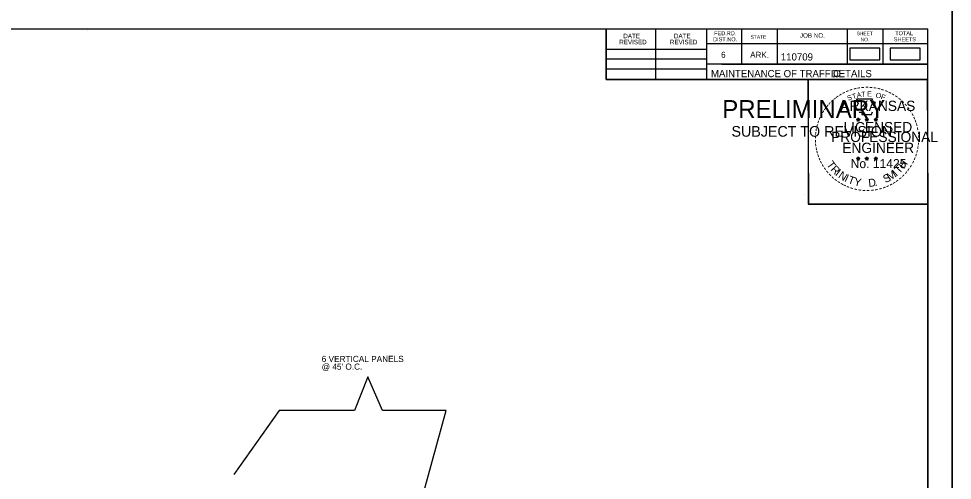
# Model space of a CAD drawing. Extents: x 2829243 to 2838161, y 467639 to 474695.
# Drawn here: x 2830244 to 2831153, y 471052 to 471502 of the extents above; entities that cross this region are included whole.
import ezdxf

# ---------------------------------------------------------------- set-up
doc = ezdxf.new("R2010")
doc.units = 0
for name, color, linetype in [('Default', 7, 'Continuous'), ('R_Border', 7, 'Continuous'), ('R_Border PE', 7, 'Continuous'), ('R_Border Prem', 7, 'Continuous'), ('R_MOT', 7, 'Continuous'), ('R_No Plot', 7, 'Continuous')]:
    doc.layers.add(name, color=color, linetype=linetype)

msp = doc.modelspace()

# ---------------------------------------------------------------- linework, layer by layer
at = {"layer": 'Default'}
for points in [[(2831053.21, 471461.81), (2831082.38, 471461.81), (2831082.38, 471473.36), (2831053.21, 471473.36)], [(2831092.56, 471461.81), (2831121.73, 471461.81), (2831121.73, 471473.36), (2831092.56, 471473.36)]]:
    msp.add_lwpolyline(points, close=True, dxfattribs=at)
at = {"layer": 'R_Border'}
for p, q in [((2829548.24, 471492.28), (2831129.14, 471492.28)), ((2830310.84, 471490.98), (2830310.84, 471490.98)), ((2830310.84, 471490.98), (2830310.84, 471490.98)), ((2830815.94, 471442.88), (2830815.94, 471492.28)), ((2830864.34, 471442.88), (2830864.34, 471492.28)), ((2830913.64, 471492.28), (2830913.64, 471442.88)), ((2830947.84, 471492.28), (2830947.84, 471457.58)), ((2830982.54, 471492.28), (2830982.54, 471457.58)), ((2831050.44, 471492.28), (2831050.44, 471457.58)), ((2831085.14, 471492.28), (2831085.14, 471457.58)), ((2831129.14, 470464.98), (2831129.14, 471492.28)), ((2831129.14, 471477.58), (2830913.64, 471477.58)), ((2831129.14, 471477.68), (2831129.14, 471477.68)), ((2830815.94, 471472.18), (2830913.64, 471472.18)), ((2830815.94, 471462.88), (2830913.64, 471462.88)), ((2831129.14, 471457.58), (2830913.64, 471457.58)), ((2830928.44, 471457.58), (2831129.14, 471457.58)), ((2830815.94, 471453.18), (2830913.64, 471453.18)), ((2831129.14, 471442.88), (2830815.94, 471442.88))]:
    msp.add_line(p, q, dxfattribs=at)
at = {"layer": 'R_Border PE'}
for p, q in [((2831059.57, 471404.16), (2831061.31, 471403.61)), ((2831059.57, 471404.16), (2831060.83, 471403.94)), ((2831059.57, 471404.16), (2831060.75, 471403.55)), ((2831060.23, 471402.12), (2831061.31, 471403.61)), ((2831060.23, 471402.12), (2831060.86, 471403.34)), ((2831060.23, 471402.12), (2831061.3, 471403.21)), ((2831061.31, 471405.43), (2831061.11, 471404.17)), ((2831062.38, 471402.12), (2831061.3, 471403.19)), ((2831061.31, 471403.61), (2831061.31, 471405.43)), ((2831061.31, 471405.43), (2831061.56, 471404.18)), ((2831063.05, 471404.16), (2831061.31, 471403.61)), ((2831062.38, 471402.12), (2831061.31, 471403.61)), ((2831063.05, 471404.16), (2831061.62, 471403.92)), ((2831062.38, 471402.12), (2831061.69, 471403.58)), ((2831063.05, 471404.16), (2831062.03, 471403.65)), ((2831067.92, 471404.16), (2831069.66, 471403.61)), ((2831067.92, 471404.16), (2831069.18, 471403.94)), ((2831067.92, 471404.16), (2831069.1, 471403.55)), ((2831068.58, 471402.12), (2831069.66, 471403.61)), ((2831068.58, 471402.12), (2831069.21, 471403.34)), ((2831068.58, 471402.12), (2831069.65, 471403.21)), ((2831069.66, 471405.43), (2831069.46, 471404.17)), ((2831070.73, 471402.12), (2831069.65, 471403.19)), ((2831069.66, 471403.61), (2831069.66, 471405.43)), ((2831069.66, 471405.43), (2831069.91, 471404.18)), ((2831071.4, 471404.16), (2831069.66, 471403.61)), ((2831070.73, 471402.12), (2831069.66, 471403.61)), ((2831071.4, 471404.16), (2831069.97, 471403.92)), ((2831070.73, 471402.12), (2831070.04, 471403.58)), ((2831071.4, 471404.16), (2831070.38, 471403.65)), ((2831076.74, 471404.1), (2831078.48, 471403.55)), ((2831076.74, 471404.1), (2831078, 471403.88)), ((2831076.74, 471404.1), (2831077.92, 471403.49)), ((2831077.4, 471402.06), (2831078.48, 471403.55)), ((2831077.4, 471402.06), (2831078.03, 471403.28)), ((2831077.4, 471402.06), (2831078.47, 471403.15)), ((2831078.48, 471405.37), (2831078.28, 471404.11)), ((2831079.55, 471402.06), (2831078.47, 471403.13)), ((2831078.48, 471403.55), (2831078.48, 471405.37)), ((2831078.48, 471405.37), (2831078.73, 471404.12)), ((2831080.22, 471404.1), (2831078.48, 471403.55)), ((2831079.55, 471402.06), (2831078.48, 471403.55)), ((2831080.22, 471404.1), (2831078.79, 471403.86)), ((2831079.55, 471402.06), (2831078.86, 471403.52)), ((2831080.22, 471404.1), (2831079.2, 471403.59)), ((2831059.55, 471366.3), (2831061.29, 471365.74)), ((2831059.55, 471366.3), (2831060.81, 471366.07)), ((2831059.55, 471366.3), (2831060.73, 471365.69)), ((2831060.21, 471364.26), (2831061.29, 471365.74)), ((2831060.21, 471364.26), (2831060.84, 471365.48)), ((2831060.21, 471364.26), (2831061.28, 471365.34)), ((2831061.29, 471367.57), (2831061.09, 471366.31)), ((2831062.36, 471364.26), (2831061.28, 471365.33)), ((2831061.29, 471365.74), (2831061.29, 471367.57)), ((2831061.29, 471367.57), (2831061.54, 471366.32)), ((2831063.03, 471366.3), (2831061.29, 471365.74)), ((2831062.36, 471364.26), (2831061.29, 471365.74)), ((2831063.03, 471366.3), (2831061.6, 471366.05)), ((2831062.36, 471364.26), (2831061.67, 471365.71)), ((2831063.03, 471366.3), (2831062.01, 471365.79)), ((2831067.89, 471366.3), (2831069.64, 471365.74)), ((2831067.89, 471366.3), (2831069.16, 471366.07)), ((2831067.89, 471366.3), (2831069.08, 471365.69)), ((2831068.56, 471364.26), (2831069.64, 471365.74)), ((2831068.56, 471364.26), (2831069.19, 471365.48)), ((2831068.56, 471364.26), (2831069.63, 471365.34)), ((2831069.64, 471367.57), (2831069.43, 471366.31)), ((2831070.7, 471364.26), (2831069.63, 471365.33)), ((2831069.64, 471365.74), (2831069.64, 471367.57)), ((2831069.64, 471367.57), (2831069.88, 471366.32)), ((2831071.37, 471366.3), (2831069.64, 471365.74)), ((2831070.7, 471364.26), (2831069.64, 471365.74)), ((2831071.37, 471366.3), (2831069.94, 471366.05)), ((2831070.7, 471364.26), (2831070.02, 471365.71)), ((2831071.37, 471366.3), (2831070.35, 471365.79)), ((2831076.73, 471366.25), (2831078.47, 471365.69)), ((2831076.73, 471366.25), (2831077.99, 471366.02)), ((2831076.73, 471366.25), (2831077.91, 471365.64)), ((2831077.39, 471364.21), (2831078.47, 471365.69)), ((2831077.39, 471364.21), (2831078.02, 471365.43)), ((2831077.39, 471364.21), (2831078.46, 471365.29)), ((2831078.47, 471367.52), (2831078.27, 471366.26)), ((2831079.54, 471364.21), (2831078.46, 471365.28)), ((2831078.47, 471365.69), (2831078.47, 471367.52)), ((2831078.47, 471367.52), (2831078.72, 471366.27)), ((2831080.21, 471366.25), (2831078.47, 471365.69)), ((2831079.54, 471364.21), (2831078.47, 471365.69)), ((2831080.21, 471366.25), (2831078.78, 471366)), ((2831079.54, 471364.21), (2831078.85, 471365.66)), ((2831080.21, 471366.25), (2831079.19, 471365.74))]:
    msp.add_line(p, q, dxfattribs=at)
for points in [[(2831059.77, 471423.55), (2831061.12, 471419.42)], [(2831077.33, 471418.94), (2831078.04, 471420.36), (2831074.61, 471420.24), (2831075.35, 471423.55), (2831059.77, 471423.55)], [(2831062.23, 471411.44), (2831062.23, 471411), (2831065.05, 471410.91), (2831064.78, 471408.54), (2831074.13, 471408.54), (2831075.13, 471411.22)], [(2831061.31, 471405.43), (2831062.38, 471402.12), (2831059.57, 471404.16), (2831063.05, 471404.16), (2831060.23, 471402.12), (2831061.31, 471405.43)], [(2831069.66, 471405.43), (2831070.73, 471402.12), (2831067.92, 471404.16), (2831071.4, 471404.16), (2831068.58, 471402.12), (2831069.66, 471405.43)], [(2831078.48, 471405.37), (2831079.55, 471402.06), (2831076.74, 471404.1), (2831080.22, 471404.1), (2831077.4, 471402.06), (2831078.48, 471405.37)], [(2831061.29, 471367.57), (2831062.36, 471364.26), (2831059.55, 471366.3), (2831063.03, 471366.3), (2831060.21, 471364.26), (2831061.29, 471367.57)], [(2831069.64, 471367.57), (2831070.7, 471364.26), (2831067.89, 471366.3), (2831071.37, 471366.3), (2831068.56, 471364.26), (2831069.64, 471367.57)], [(2831078.47, 471367.52), (2831079.54, 471364.21), (2831076.73, 471366.25), (2831080.21, 471366.25), (2831077.39, 471364.21), (2831078.47, 471367.52)]]:
    msp.add_lwpolyline(points, dxfattribs=at)
for centre, radius in [((2831061.31, 471403.6), 0.861), ((2831061.31, 471403.6), 0.723), ((2831061.31, 471403.6), 0.579), ((2831061.31, 471403.6), 0.495), ((2831061.31, 471403.6), 0.374), ((2831061.31, 471403.6), 0.248), ((2831061.31, 471403.6), 0.148), ((2831069.66, 471403.6), 0.861), ((2831069.66, 471403.6), 0.723), ((2831069.66, 471403.6), 0.579), ((2831069.66, 471403.6), 0.495), ((2831069.66, 471403.6), 0.374), ((2831069.66, 471403.6), 0.248), ((2831069.66, 471403.6), 0.148), ((2831078.48, 471403.54), 0.861), ((2831078.48, 471403.54), 0.723), ((2831078.48, 471403.54), 0.579), ((2831078.48, 471403.54), 0.495), ((2831078.48, 471403.54), 0.374), ((2831078.48, 471403.54), 0.248), ((2831078.48, 471403.54), 0.148), ((2831061.29, 471365.74), 0.861), ((2831061.29, 471365.74), 0.723), ((2831061.29, 471365.74), 0.579), ((2831061.29, 471365.74), 0.495), ((2831061.29, 471365.74), 0.374), ((2831061.29, 471365.74), 0.248), ((2831061.29, 471365.74), 0.148), ((2831069.63, 471365.74), 0.861), ((2831069.63, 471365.74), 0.723), ((2831069.63, 471365.74), 0.579), ((2831069.63, 471365.74), 0.495), ((2831069.63, 471365.74), 0.374), ((2831069.63, 471365.74), 0.248), ((2831069.63, 471365.74), 0.148), ((2831078.47, 471365.69), 0.861), ((2831078.47, 471365.69), 0.723), ((2831078.47, 471365.69), 0.579), ((2831078.47, 471365.69), 0.495), ((2831078.47, 471365.69), 0.374), ((2831078.47, 471365.69), 0.248), ((2831078.47, 471365.69), 0.148)]:
    msp.add_circle(centre, radius, dxfattribs=at)
at = {"layer": 'R_MOT'}
msp.add_lwpolyline([(2830620.35, 470975.07), (2830660.32, 471120.5), (2830598.07, 471120.5), (2830584.04, 471153.28), (2830571.05, 471120.5), (2830497.71, 471120.5), (2830453.58, 471057.96)], dxfattribs=at)
at = {"layer": 'R_No Plot'}
msp.add_line((2831009.31, 471330.61), (2831009.31, 471330.61), dxfattribs=at)
for points in [[(2829486.2, 471511.76), (2831152.9, 471511.76), (2831152.9, 470445.07), (2829486.2, 470445.07)], [(2831152.9, 471511.76), (2832819.6, 471511.76), (2832819.6, 470445.07), (2831152.9, 470445.07)], [(2830717.84, 471492.28), (2830815.94, 471492.28), (2830815.94, 471442.88), (2830896.5, 471442.88), (2831012.5, 471442.88), (2831012.5, 471321.22), (2831129.14, 471321.22), (2831129.14, 470464.98), (2829548.24, 470464.98), (2829548.24, 471492.28)], [(2831012.5, 471442.88), (2831128.54, 471442.88), (2831129.14, 471321.22), (2831013.1, 471321.22)]]:
    msp.add_lwpolyline(points, close=True, dxfattribs=at)

# ---------------------------------------------------------------- texts
at = {"layer": 'R_Border'}
for s, height, p in [('DATE', 4.396, (2830832.63, 471482.97)), ('DATE', 4.396, (2830881.93, 471482.97)), ('DIST.NO.', 3.91, (2830920.04, 471479.98)), ('FED.RD.', 3.91, (2830921.04, 471485.88)), ('STATE', 3.42, (2830956.64, 471482.48)), ('JOB NO.', 4.396, (2831004.54, 471483.48)), ('SHEET', 3.42, (2831059.74, 471485.88)), ('NO.', 3.42, (2831063.64, 471479.98)), ('SHEETS', 3.91, (2831095.94, 471479.98)), ('TOTAL', 3.91, (2831097.34, 471485.88)), ('REVISED', 4.396, (2830828.73, 471477.07)), ('REVISED', 4.396, (2830878.03, 471477.07)), ('6', 5.86, (2830927.84, 471463.88)), ('ARK.', 5.861, (2830956.14, 471463.88)), ('110709', 7, (2830986.02, 471461.28)), ('MAINTENANCE OF TRAFFIC', 7, (2830917.96, 471445.04)), (' DETAILS', 7, (2831032.95, 471445.04))]:
    msp.add_text(s, height=height, dxfattribs=at).set_placement(p)
at = {"layer": 'R_Border PE'}
for s, height, rotation, p in [('-', 8, 34.06357, (2831044.19, 471424.41)), ('-', 8, 28.79182, (2831047.18, 471426.26)), ('-', 8, 24.30721, (2831050.34, 471427.84)), ('-', 8, 19.17608, (2831053.51, 471429.19)), ('T', 5, 16.4036, (2831056.12, 471423.6)), ('-', 8, 13.63015, (2831057.26, 471430.39)), ('A', 5, 11.21318, (2831060.25, 471424.85)), ('-', 8, 10.21935, (2831060.65, 471431.2)), ('T', 5, 6.02276, (2831064.49, 471425.68)), ('-', 8, 5.89682, (2831064.3, 471431.75)), ('-', 8, 0.18623, (2831068.16, 471432.11)), ('E', 5, 0.83234, (2831070.02, 471426.23)), ('-', 8, 357.74304, (2831071.77, 471432.05)), ('-', 8, 352.16172, (2831075.49, 471431.77)), ('O', 5, 350.4515, (2831078.04, 471425.18)), ('-', 8, 347.20489, (2831079.09, 471431.2)), ('-', 8, 342.3362, (2831082.26, 471430.42)), ('-', 8, 337.85509, (2831085.94, 471429.31)), ('-', 8, 334.12109, (2831089.09, 471427.95)), ('-', 8, 329.64089, (2831091.99, 471426.54)), ('-', 8, 48.42305, (2831034.52, 471416.07)), ('-', 8, 42.96224, (2831036.76, 471418.46)), ('-', 8, 38.95066, (2831038.92, 471420.54)), ('-', 8, 36.23174, (2831041.3, 471422.43)), ('S', 5, 21.59401, (2831051.55, 471421.94)), ('F', 5, 340.07066, (2831082.81, 471424.04)), ('-', 8, 325.86266, (2831095.2, 471424.73)), ('-', 8, 320.52971, (2831098.25, 471422.6)), ('-', 8, 315.57859, (2831101.25, 471420.16)), ('-', 8, 58.07063, (2831028.81, 471408.17)), ('-', 8, 54.23247, (2831030.44, 471410.8)), ('-', 8, 50.61417, (2831032.5, 471413.64)), ('-', 8, 309.87973, (2831104.09, 471417.41)), ('-', 8, 306.65218, (2831106.72, 471414.4)), ('-', 7, 303.67529, (2831109.15, 471411.56)), ('-', 8, 72.39447, (2831024.86, 471398.89)), ('-', 8, 67.77427, (2831025.95, 471402.04)), ('-', 8, 62.87135, (2831027.25, 471405.1)), ('-', 8, 299.66835, (2831110.74, 471408.53)), ('-', 8, 294.66279, (2831112.36, 471405.47)), ('-', 8, 290.57283, (2831113.65, 471402.58)), ('-', 8, 81.20126, (2831023.21, 471391.76)), ('-', 8, 75.46096, (2831023.87, 471395.32)), ('-', 8, 285.12326, (2831114.82, 471399.68)), ('-', 8, 280.54934, (2831115.82, 471395.97)), ('-', 8, 94.19588, (2831022.88, 471381.17)), ('-', 8, 89.06224, (2831022.71, 471384.8)), ('-', 8, 85.18634, (2831022.83, 471388.3)), ('-', 8, 276.59616, (2831116.63, 471392.13)), ('-', 8, 274.33011, (2831116.93, 471388.52)), ('-', 8, 269.94067, (2831117.1, 471385.36)), ('-', 8, 98.94793, (2831023.24, 471377.84)), ('-', 8, 101.71495, (2831023.92, 471374.17)), ('-', 8, 255.7626, (2831116.1, 471375.37)), ('-', 8, 260.99529, (2831116.65, 471378.76)), ('-', 8, 263.5172, (2831117, 471382.03)), ('-', 8, 105.45785, (2831024.73, 471371.2)), ('-', 8, 109.08742, (2831025.8, 471368.04)), ('-', 8, 114.06432, (2831027.07, 471365.06)), ('-', 8, 247.88866, (2831114.08, 471368.41)), ('-', 8, 252.86809, (2831115.19, 471371.77)), ('-', 8, 115.72885, (2831028.6, 471361.97)), ('-', 8, 120.44712, (2831030.38, 471359.04)), ('-', 8, 125.89344, (2831032.4, 471356.24)), ('T', 7.7, 306.04056, (2831030.09, 471359.93)), ('R', 7.7, 314.00497, (2831033.9, 471354.69)), ('T', 7.7, 46.64442, (2831101.24, 471350.39)), ('H', 7.7, 54.60883, (2831105.69, 471355.11)), ('-', 8, 233.84524, (2831108.79, 471358.24)), ('-', 8, 239.07125, (2831110.8, 471361.5)), ('-', 8, 244.61971, (2831112.77, 471365.26)), ('-', 8, 130.71812, (2831034.71, 471353.48)), ('-', 8, 134.22381, (2831037.29, 471350.75)), ('-', 8, 138.93382, (2831039.92, 471348.43)), ('I', 7.7, 321.96938, (2831038.4, 471350.03)), ('N', 7.7, 326.50021, (2831041.24, 471347.67)), ('I', 7.7, 335.36034, (2831047.28, 471343.74)), ('T', 7.7, 339.89117, (2831050.59, 471342.11)), ('Y', 7.7, 347.85558, (2831056.67, 471339.88)), ('S', 7.7, 26.9312, (2831087.82, 471341.74)), ('M', 7.7, 32.65632, (2831092.01, 471343.77)), ('I', 7.7, 42.11359, (2831098.43, 471348)), ('-', 8, 221.08509, (2831101.63, 471350.04)), ('-', 8, 225.76533, (2831104.24, 471352.59)), ('-', 8, 231.25377, (2831106.64, 471355.41)), ('-', 8, 144.64634, (2831042.7, 471346.4)), ('-', 8, 148.08978, (2831045.5, 471344.55)), ('-', 8, 151.57039, (2831048.4, 471342.92)), ('-', 8, 154.60019, (2831051.01, 471341.69)), ('-', 8, 158.56121, (2831054.13, 471340.42)), ('D', 7.7, 6.39691, (2831071.59, 471338.09)), ('.', 7.7, 13.76417, (2831077.56, 471338.72)), ('-', 8, 200.71842, (2831087.21, 471341.06)), ('-', 8, 204.25161, (2831090.31, 471342.42)), ('-', 8, 207.35684, (2831093.43, 471344.02)), ('-', 8, 212.24909, (2831096.22, 471345.75)), ('-', 8, 215.73633, (2831098.89, 471347.68)), ('-', 8, 162.79826, (2831057.56, 471339.35)), ('-', 8, 167.55551, (2831061.14, 471338.53)), ('-', 8, 173.11546, (2831065, 471337.98)), ('-', 8, 176.51827, (2831068.74, 471337.72)), ('-', 8, 181.59176, (2831072.46, 471337.81)), ('-', 8, 185.81666, (2831076.5, 471338.19)), ('-', 8, 191.28576, (2831080.18, 471338.85)), ('-', 8, 195.47429, (2831083.83, 471339.85))]:
    msp.add_text(s, height=height, rotation=rotation, dxfattribs=at).set_placement(p)
for s, height, p in [('ARKANSAS', 10, (2831044.04, 471412.11)), ('LICENSED', 10, (2831047.02, 471391.37)), ('DWB', 0.05, (2831061.25, 471403.58)), ('DWB', 0.05, (2831069.6, 471403.58)), ('DWB', 0.05, (2831078.42, 471403.53)), ('PROFESSIONAL', 10, (2831034.91, 471381.85)), ('ENGINEER', 10, (2831045.84, 471371.22)), ('No. 11425', 8.785, (2831053.98, 471356.47)), ('DWB', 0.05, (2831061.23, 471365.72)), ('DWB', 0.05, (2831069.57, 471365.72)), ('DWB', 0.05, (2831078.41, 471365.67))]:
    msp.add_text(s, height=height, dxfattribs=at).set_placement(p)
at = {"layer": 'R_Border Prem'}
for s, height, p in [('PRELIMINARY', 17.5, (2830928.9, 471405.2)), ('DWB', 0.05, (2830932.63, 471414.45)), ('SUBJECT TO REVISION', 10.3756, (2830937.94, 471387.06))]:
    msp.add_text(s, height=height, dxfattribs=at).set_placement(p)
at = {"layer": 'R_MOT'}
for s, p in [('6 VERTICAL PANELS', (2830539.01, 471167.65)), ("@ 45' O.C.", (2830539.01, 471160.14))]:
    msp.add_text(s, height=6, rotation=0.00554, dxfattribs=at).set_placement(p)

doc.saveas('drawing.dxf')
